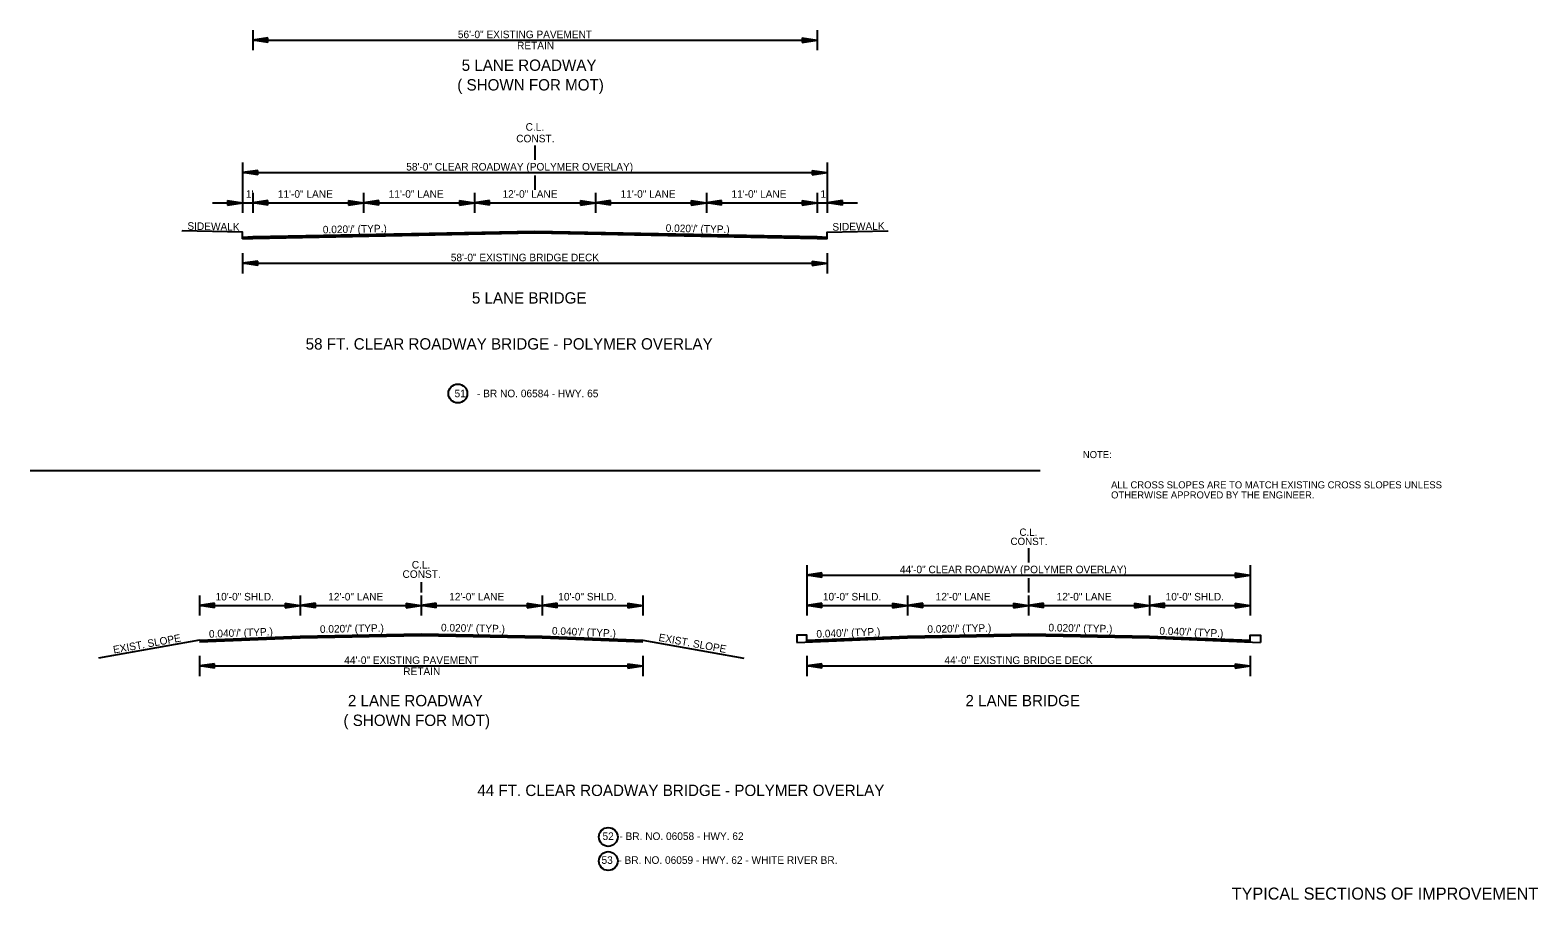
# Model space of a CAD drawing. Extents: x 550980 to 1930787, y -1972975 to 596640.
# Drawn here: x 551050 to 552546, y -1969226 to -1968363 of the extents above; entities that cross this region are included whole.
import ezdxf

# ---------------------------------------------------------------- set-up
doc = ezdxf.new("R2010")
doc.units = 0
for name, color, linetype in [('R_Border', 7, 'Continuous'), ('R_Border Notes', 7, 'Continuous'), ('R_Draft', 7, 'Continuous')]:
    doc.layers.add(name, color=color, linetype=linetype)

# ---------------------------------------------------------------- blocks, each defined once
blk = doc.blocks.new('ARROW')
at = {"layer": 'R_Draft'}
for p, q in [((-2, 0.3), (0, 0)), ((-2, 0.3), (-2, -0.3)), ((-2, 0.25), (-0.334, 0)), ((-2, 0.199), (-0.678, 0)), ((-2, 0.149), (-1.011, 0)), ((-2, 0.097), (-1.35, 0)), ((-2, 0.047), (-1.684, 0)), ((-2, -0.3), (0, 0)), ((-2, -0.098), (-1.35, 0)), ((-2, -0.199), (-0.678, 0)), ((-2, -0.25), (-0.334, 0)), ((-2, -0.149), (-1.011, 0)), ((-2, -0.047), (-1.684, 0))]:
    blk.add_line(p, q, dxfattribs=at)
blk = doc.blocks.new('BPPOLY')
at = {"layer": 'R_Border'}
blk.add_circle((0, 0), 9.34, dxfattribs=at)

msp = doc.modelspace()

# ---------------------------------------------------------------- linework, layer by layer
at = {"layer": 'R_Border'}
for p, q in [((551271.1, -1968362.7), (551271.1, -1968382.7)), ((551831.1, -1968362.7), (551831.1, -1968382.7)), ((551286.1, -1968370.5), (551271.1, -1968372.7)), ((551271.1, -1968372.7), (551831.1, -1968372.7)), ((551286.1, -1968375), (551271.1, -1968372.7)), ((551286.1, -1968370.9), (551273.6, -1968372.7)), ((551286.1, -1968374.6), (551273.6, -1968372.7)), ((551286.1, -1968371.2), (551276.2, -1968372.7)), ((551286.1, -1968374.2), (551276.2, -1968372.7)), ((551286.1, -1968371.6), (551278.7, -1968372.7)), ((551286.1, -1968373.9), (551278.7, -1968372.7)), ((551286.1, -1968372), (551281.2, -1968372.7)), ((551286.1, -1968373.5), (551281.2, -1968372.7)), ((551286.1, -1968372.4), (551283.7, -1968372.7)), ((551286.1, -1968373.1), (551283.7, -1968372.7)), ((551286.1, -1968375), (551286.1, -1968370.5)), ((551816.1, -1968370.5), (551831.1, -1968372.7)), ((551816.1, -1968370.5), (551816.1, -1968375)), ((551816.1, -1968370.9), (551828.6, -1968372.7)), ((551816.1, -1968371.2), (551826, -1968372.7)), ((551816.1, -1968371.6), (551823.5, -1968372.7)), ((551816.1, -1968372), (551821, -1968372.7)), ((551816.1, -1968372.4), (551818.5, -1968372.7)), ((551816.1, -1968375), (551831.1, -1968372.7)), ((551816.1, -1968373.5), (551821, -1968372.7)), ((551816.1, -1968374.2), (551826, -1968372.7)), ((551816.1, -1968374.6), (551828.6, -1968372.7)), ((551816.1, -1968373.9), (551823.5, -1968372.7)), ((551816.1, -1968373.1), (551818.5, -1968372.7)), ((551551.1, -1968477), (551551.1, -1968491.5)), ((551261.1, -1968494), (551261.1, -1968544)), ((551276.1, -1968501.8), (551261.1, -1968504)), ((551261.1, -1968504), (551841.1, -1968504)), ((551276.1, -1968506.3), (551261.1, -1968504)), ((551276.1, -1968502.1), (551263.6, -1968504)), ((551276.1, -1968505.9), (551263.6, -1968504)), ((551276.1, -1968502.5), (551266.2, -1968504)), ((551276.1, -1968505.5), (551266.2, -1968504)), ((551276.1, -1968502.9), (551268.7, -1968504)), ((551276.1, -1968505.1), (551268.7, -1968504)), ((551276.1, -1968503.3), (551271.2, -1968504)), ((551276.1, -1968504.7), (551271.2, -1968504)), ((551276.1, -1968503.7), (551273.7, -1968504)), ((551276.1, -1968504.4), (551273.7, -1968504)), ((551276.1, -1968506.3), (551276.1, -1968501.8)), ((551826.1, -1968501.8), (551841.1, -1968504)), ((551826.1, -1968501.8), (551826.1, -1968506.3)), ((551826.1, -1968502.1), (551838.6, -1968504)), ((551826.1, -1968502.5), (551836, -1968504)), ((551826.1, -1968502.9), (551833.5, -1968504)), ((551826.1, -1968503.3), (551831, -1968504)), ((551826.1, -1968503.7), (551828.5, -1968504)), ((551826.1, -1968506.3), (551841.1, -1968504)), ((551826.1, -1968504.8), (551831, -1968504)), ((551826.1, -1968505.5), (551836, -1968504)), ((551826.1, -1968505.9), (551838.6, -1968504)), ((551826.1, -1968505.1), (551833.5, -1968504)), ((551826.1, -1968504.4), (551828.5, -1968504)), ((551841.1, -1968494), (551841.1, -1968544)), ((551551.1, -1968507), (551551.1, -1968521)), ((551231.1, -1968534), (551871.1, -1968534)), ((551246.1, -1968531.8), (551261.1, -1968534)), ((551246.1, -1968531.8), (551246.1, -1968536.3)), ((551246.1, -1968532.1), (551258.6, -1968534)), ((551246.1, -1968532.5), (551256, -1968534)), ((551246.1, -1968532.9), (551253.5, -1968534)), ((551246.1, -1968533.3), (551251, -1968534)), ((551246.1, -1968533.7), (551248.5, -1968534)), ((551246.1, -1968536.3), (551261.1, -1968534)), ((551246.1, -1968534.8), (551251, -1968534)), ((551246.1, -1968535.5), (551256, -1968534)), ((551246.1, -1968535.9), (551258.6, -1968534)), ((551246.1, -1968535.1), (551253.5, -1968534)), ((551246.1, -1968534.4), (551248.5, -1968534)), ((551271.1, -1968524), (551271.1, -1968544)), ((551286.1, -1968531.8), (551271.1, -1968534)), ((551286.1, -1968536.3), (551271.1, -1968534)), ((551286.1, -1968532.1), (551273.6, -1968534)), ((551286.1, -1968535.9), (551273.6, -1968534)), ((551286.1, -1968532.5), (551276.2, -1968534)), ((551286.1, -1968535.5), (551276.2, -1968534)), ((551286.1, -1968532.9), (551278.7, -1968534)), ((551286.1, -1968535.1), (551278.7, -1968534)), ((551286.1, -1968533.3), (551281.2, -1968534)), ((551286.1, -1968534.7), (551281.2, -1968534)), ((551286.1, -1968533.7), (551283.7, -1968534)), ((551286.1, -1968534.4), (551283.7, -1968534)), ((551286.1, -1968536.3), (551286.1, -1968531.8)), ((551366.1, -1968531.8), (551381.1, -1968534)), ((551366.1, -1968531.8), (551366.1, -1968536.3)), ((551366.1, -1968532.1), (551378.6, -1968534)), ((551366.1, -1968532.5), (551376, -1968534)), ((551366.1, -1968532.9), (551373.5, -1968534)), ((551366.1, -1968533.3), (551371, -1968534)), ((551366.1, -1968533.7), (551368.5, -1968534)), ((551366.1, -1968536.3), (551381.1, -1968534)), ((551366.1, -1968534.8), (551371, -1968534)), ((551366.1, -1968535.5), (551376, -1968534)), ((551366.1, -1968535.9), (551378.6, -1968534)), ((551366.1, -1968535.1), (551373.5, -1968534)), ((551366.1, -1968534.4), (551368.5, -1968534)), ((551381.1, -1968524), (551381.1, -1968544)), ((551396.1, -1968531.8), (551381.1, -1968534)), ((551396.1, -1968536.3), (551381.1, -1968534)), ((551396.1, -1968532.1), (551383.6, -1968534)), ((551396.1, -1968535.9), (551383.6, -1968534)), ((551396.1, -1968532.5), (551386.2, -1968534)), ((551396.1, -1968535.5), (551386.2, -1968534)), ((551396.1, -1968532.9), (551388.7, -1968534)), ((551396.1, -1968535.1), (551388.7, -1968534)), ((551396.1, -1968533.3), (551391.2, -1968534)), ((551396.1, -1968534.7), (551391.2, -1968534)), ((551396.1, -1968533.7), (551393.7, -1968534)), ((551396.1, -1968534.4), (551393.7, -1968534)), ((551396.1, -1968536.3), (551396.1, -1968531.8)), ((551476.1, -1968531.8), (551491.1, -1968534)), ((551476.1, -1968531.8), (551476.1, -1968536.3)), ((551476.1, -1968532.1), (551488.6, -1968534)), ((551476.1, -1968532.5), (551486, -1968534)), ((551476.1, -1968532.9), (551483.5, -1968534)), ((551476.1, -1968533.3), (551481, -1968534)), ((551476.1, -1968533.7), (551478.5, -1968534)), ((551476.1, -1968536.3), (551491.1, -1968534)), ((551476.1, -1968534.8), (551481, -1968534)), ((551476.1, -1968535.5), (551486, -1968534)), ((551476.1, -1968535.9), (551488.6, -1968534)), ((551476.1, -1968535.1), (551483.5, -1968534)), ((551476.1, -1968534.4), (551478.5, -1968534)), ((551491.1, -1968524), (551491.1, -1968544)), ((551506.1, -1968531.8), (551491.1, -1968534)), ((551506.1, -1968536.3), (551491.1, -1968534)), ((551506.1, -1968532.1), (551493.6, -1968534)), ((551506.1, -1968535.9), (551493.6, -1968534)), ((551506.1, -1968532.5), (551496.2, -1968534)), ((551506.1, -1968535.5), (551496.2, -1968534)), ((551506.1, -1968532.9), (551498.7, -1968534)), ((551506.1, -1968535.1), (551498.7, -1968534)), ((551506.1, -1968533.3), (551501.2, -1968534)), ((551506.1, -1968534.7), (551501.2, -1968534)), ((551506.1, -1968533.7), (551503.7, -1968534)), ((551506.1, -1968534.4), (551503.7, -1968534)), ((551506.1, -1968536.3), (551506.1, -1968531.8)), ((551596.1, -1968531.8), (551611.1, -1968534)), ((551596.1, -1968531.8), (551596.1, -1968536.3)), ((551596.1, -1968532.1), (551608.6, -1968534)), ((551596.1, -1968532.5), (551606, -1968534)), ((551596.1, -1968532.9), (551603.5, -1968534)), ((551596.1, -1968533.3), (551601, -1968534)), ((551596.1, -1968533.7), (551598.5, -1968534)), ((551596.1, -1968536.3), (551611.1, -1968534)), ((551596.1, -1968534.8), (551601, -1968534)), ((551596.1, -1968535.5), (551606, -1968534)), ((551596.1, -1968535.9), (551608.6, -1968534)), ((551596.1, -1968535.1), (551603.5, -1968534)), ((551596.1, -1968534.4), (551598.5, -1968534)), ((551611.1, -1968524), (551611.1, -1968544)), ((551626.1, -1968531.8), (551611.1, -1968534)), ((551626.1, -1968536.3), (551611.1, -1968534)), ((551626.1, -1968532.1), (551613.6, -1968534)), ((551626.1, -1968535.9), (551613.6, -1968534)), ((551626.1, -1968532.5), (551616.2, -1968534)), ((551626.1, -1968535.5), (551616.2, -1968534)), ((551626.1, -1968532.9), (551618.7, -1968534)), ((551626.1, -1968535.1), (551618.7, -1968534)), ((551626.1, -1968533.3), (551621.2, -1968534)), ((551626.1, -1968534.7), (551621.2, -1968534)), ((551626.1, -1968533.7), (551623.7, -1968534)), ((551626.1, -1968534.4), (551623.7, -1968534)), ((551626.1, -1968536.3), (551626.1, -1968531.8)), ((551706.1, -1968531.8), (551721.1, -1968534)), ((551706.1, -1968531.8), (551706.1, -1968536.3)), ((551706.1, -1968532.1), (551718.6, -1968534)), ((551706.1, -1968532.5), (551716, -1968534)), ((551706.1, -1968532.9), (551713.5, -1968534)), ((551706.1, -1968533.3), (551711, -1968534)), ((551706.1, -1968533.7), (551708.5, -1968534)), ((551706.1, -1968536.3), (551721.1, -1968534)), ((551706.1, -1968534.8), (551711, -1968534)), ((551706.1, -1968535.5), (551716, -1968534)), ((551706.1, -1968535.9), (551718.6, -1968534)), ((551706.1, -1968535.1), (551713.5, -1968534)), ((551706.1, -1968534.4), (551708.5, -1968534)), ((551721.1, -1968524), (551721.1, -1968544)), ((551736.1, -1968531.8), (551721.1, -1968534)), ((551736.1, -1968536.3), (551721.1, -1968534)), ((551736.1, -1968532.1), (551723.6, -1968534)), ((551736.1, -1968535.9), (551723.6, -1968534)), ((551736.1, -1968532.5), (551726.2, -1968534)), ((551736.1, -1968535.5), (551726.2, -1968534)), ((551736.1, -1968532.9), (551728.7, -1968534)), ((551736.1, -1968535.1), (551728.7, -1968534)), ((551736.1, -1968533.3), (551731.2, -1968534)), ((551736.1, -1968534.7), (551731.2, -1968534)), ((551736.1, -1968533.7), (551733.7, -1968534)), ((551736.1, -1968534.4), (551733.7, -1968534)), ((551736.1, -1968536.3), (551736.1, -1968531.8)), ((551816.1, -1968531.8), (551831.1, -1968534)), ((551816.1, -1968531.8), (551816.1, -1968536.3)), ((551816.1, -1968532.1), (551828.6, -1968534)), ((551816.1, -1968532.5), (551826, -1968534)), ((551816.1, -1968532.9), (551823.5, -1968534)), ((551816.1, -1968533.3), (551821, -1968534)), ((551816.1, -1968533.7), (551818.5, -1968534)), ((551816.1, -1968536.3), (551831.1, -1968534)), ((551816.1, -1968534.8), (551821, -1968534)), ((551816.1, -1968535.5), (551826, -1968534)), ((551816.1, -1968535.9), (551828.6, -1968534)), ((551816.1, -1968535.1), (551823.5, -1968534)), ((551816.1, -1968534.4), (551818.5, -1968534)), ((551831.1, -1968524), (551831.1, -1968544)), ((551856.1, -1968531.8), (551841.1, -1968534)), ((551856.1, -1968536.3), (551841.1, -1968534)), ((551856.1, -1968532.1), (551843.6, -1968534)), ((551856.1, -1968535.9), (551843.6, -1968534)), ((551856.1, -1968532.5), (551846.2, -1968534)), ((551856.1, -1968535.5), (551846.2, -1968534)), ((551856.1, -1968532.9), (551848.7, -1968534)), ((551856.1, -1968535.1), (551848.7, -1968534)), ((551856.1, -1968533.3), (551851.2, -1968534)), ((551856.1, -1968534.7), (551851.2, -1968534)), ((551856.1, -1968533.7), (551853.7, -1968534)), ((551856.1, -1968534.4), (551853.7, -1968534)), ((551856.1, -1968536.3), (551856.1, -1968531.8)), ((551261.1, -1968584), (551261.1, -1968604)), ((551276.1, -1968591.8), (551261.1, -1968594)), ((551276.1, -1968592.1), (551263.6, -1968594)), ((551276.1, -1968592.5), (551266.2, -1968594)), ((551276.1, -1968592.9), (551268.7, -1968594)), ((551276.1, -1968593.3), (551271.2, -1968594)), ((551276.1, -1968593.7), (551273.7, -1968594)), ((551276.1, -1968596.3), (551276.1, -1968591.8)), ((551826.1, -1968591.8), (551841.1, -1968594)), ((551826.1, -1968591.8), (551826.1, -1968596.3)), ((551826.1, -1968592.1), (551838.6, -1968594)), ((551826.1, -1968592.5), (551836, -1968594)), ((551826.1, -1968592.9), (551833.5, -1968594)), ((551826.1, -1968593.3), (551831, -1968594)), ((551826.1, -1968593.7), (551828.5, -1968594)), ((551841.1, -1968584), (551841.1, -1968604)), ((551261.1, -1968594), (551841.1, -1968594)), ((551276.1, -1968596.3), (551261.1, -1968594)), ((551276.1, -1968595.9), (551263.6, -1968594)), ((551276.1, -1968595.5), (551266.2, -1968594)), ((551276.1, -1968595.1), (551268.7, -1968594)), ((551276.1, -1968594.7), (551271.2, -1968594)), ((551276.1, -1968594.4), (551273.7, -1968594)), ((551826.1, -1968596.3), (551841.1, -1968594)), ((551826.1, -1968594.8), (551831, -1968594)), ((551826.1, -1968595.5), (551836, -1968594)), ((551826.1, -1968595.9), (551838.6, -1968594)), ((551826.1, -1968595.1), (551833.5, -1968594)), ((551826.1, -1968594.4), (551828.5, -1968594)), ((551050.3, -1968799.7), (552052.2, -1968799.7)), ((552040.7, -1968876.5), (552040.7, -1968891)), ((551820.7, -1968893.5), (551820.7, -1968943.5)), ((551820.7, -1968903.5), (552260.7, -1968903.5)), ((552040.7, -1968906.5), (552040.7, -1968920.5)), ((552260.7, -1968893.5), (552260.7, -1968943.5)), ((551438.2, -1968910.5), (551438.2, -1968920.5)), ((551218.2, -1968923.5), (551218.2, -1968943.5)), ((551218.2, -1968933.5), (551658.2, -1968933.5)), ((551318.2, -1968923.5), (551318.2, -1968943.5)), ((551438.2, -1968923.5), (551438.2, -1968943.5)), ((551558.2, -1968923.5), (551558.2, -1968943.5)), ((551658.2, -1968923.5), (551658.2, -1968943.5)), ((551820.7, -1968933.5), (552260.7, -1968933.5)), ((551920.7, -1968923.5), (551920.7, -1968943.5)), ((552040.7, -1968923.5), (552040.7, -1968943.5)), ((552160.7, -1968923.5), (552160.7, -1968943.5)), ((551218.2, -1968967.9), (551118.2, -1968985.9)), ((551658.2, -1968967.9), (551758.2, -1968985.9)), ((551218.2, -1968983.5), (551218.2, -1969003.5)), ((551218.2, -1968993.5), (551658.2, -1968993.5)), ((551658.2, -1968983.5), (551658.2, -1969003.5)), ((551820.7, -1968983.5), (551820.7, -1969003.5)), ((551820.7, -1968993.5), (552260.7, -1968993.5)), ((552260.7, -1968983.5), (552260.7, -1969003.5))]:
    msp.add_line(p, q, dxfattribs=at)
for points in [[(551261.1, -1968569.8), (551261.1, -1968563), (551201.1, -1968561.8), (551201.1, -1968561.8)], [(551261.1, -1968568), (551271.1, -1968567.6), (551551.1, -1968562), (551831.1, -1968567.6), (551841.1, -1968568)], [(551261.1, -1968568.3), (551271.1, -1968567.9), (551551.1, -1968562.3), (551831.1, -1968567.9), (551841.1, -1968568.3)], [(551261.1, -1968568.6), (551271.1, -1968568.2), (551551.1, -1968562.6), (551831.1, -1968568.2), (551841.1, -1968568.6)], [(551261.1, -1968568.9), (551271.1, -1968568.5), (551551.1, -1968562.9), (551831.1, -1968568.5), (551841.1, -1968568.9)], [(551261.1, -1968569.2), (551271.1, -1968568.8), (551551.1, -1968563.2), (551831.1, -1968568.8), (551841.1, -1968569.2)], [(551261.1, -1968569.5), (551271.1, -1968569.1), (551551.1, -1968563.5), (551831.1, -1968569.1), (551841.1, -1968569.5)], [(551261.1, -1968569.8), (551271.1, -1968569.4), (551551.1, -1968563.8), (551831.1, -1968569.4), (551841.1, -1968569.8)], [(551841.1, -1968569.8), (551841.1, -1968563), (551901.1, -1968561.8), (551901.1, -1968561.8)], [(551218.2, -1968967.9), (551318.2, -1968963.9), (551438.2, -1968961.5), (551558.2, -1968963.9), (551658.2, -1968967.9)], [(551218.2, -1968968.2), (551318.2, -1968964.2), (551438.2, -1968961.8), (551558.2, -1968964.2), (551658.2, -1968968.2)], [(551218.2, -1968968.5), (551318.2, -1968964.5), (551438.2, -1968962.1), (551558.2, -1968964.5), (551658.2, -1968968.5)], [(551218.2, -1968968.8), (551318.2, -1968964.8), (551438.2, -1968962.4), (551558.2, -1968964.8), (551658.2, -1968968.8)], [(551218.2, -1968969.1), (551318.2, -1968965.1), (551438.2, -1968962.7), (551558.2, -1968965.1), (551658.2, -1968969.1)], [(551218.2, -1968969.4), (551318.2, -1968965.4), (551438.2, -1968963), (551558.2, -1968965.4), (551658.2, -1968969.4)], [(551218.2, -1968969.7), (551318.2, -1968965.7), (551438.2, -1968963.3), (551558.2, -1968965.7), (551658.2, -1968969.7)], [(551820.7, -1968969.4), (551820.7, -1968962.9), (551810.7, -1968962.9), (551810.7, -1968970.1)], [(551810.7, -1968970.1), (551920.7, -1968965.7), (552040.7, -1968963.3), (552160.7, -1968965.7), (552270.7, -1968970.1)], [(551820.7, -1968967.9), (551920.7, -1968963.9), (552040.7, -1968961.5), (552160.7, -1968963.9), (552260.7, -1968967.9)], [(551820.7, -1968968.2), (551920.7, -1968964.2), (552040.7, -1968961.8), (552160.7, -1968964.2), (552260.7, -1968968.2)], [(551820.7, -1968968.5), (551920.7, -1968964.5), (552040.7, -1968962.1), (552160.7, -1968964.5), (552260.7, -1968968.5)], [(551820.7, -1968968.8), (551920.7, -1968964.8), (552040.7, -1968962.4), (552160.7, -1968964.8), (552260.7, -1968968.8)], [(551820.7, -1968969.1), (551920.7, -1968965.1), (552040.7, -1968962.7), (552160.7, -1968965.1), (552260.7, -1968969.1)], [(551820.7, -1968969.4), (551920.7, -1968965.4), (552040.7, -1968963), (552160.7, -1968965.4), (552260.7, -1968969.4)], [(552260.7, -1968970.1), (552260.7, -1968962.9), (552270.7, -1968962.9), (552270.7, -1968970.1)]]:
    msp.add_lwpolyline(points, dxfattribs=at)
for centre in [(551623.8, -1969163.1), (551623.8, -1969187)]:
    msp.add_circle(centre, 9.34, dxfattribs=at)

# ---------------------------------------------------------------- block references
msp.add_blockref('BPPOLY', (551474.6, -1968723.2), dxfattribs=at)
at = {"layer": 'R_Border', "xscale": 7.5, "yscale": 7.5, "rotation": 180}
for p in [(551820.7, -1968903.5), (551218.2, -1968933.5), (551318.2, -1968933.5), (551438.2, -1968933.5), (551558.2, -1968933.5), (551820.7, -1968933.5), (551920.7, -1968933.5), (552040.7, -1968933.5), (552160.7, -1968933.5), (551218.2, -1968993.5), (551820.7, -1968993.5)]:
    msp.add_blockref('ARROW', p, dxfattribs=at)
at = {"layer": 'R_Border', "xscale": 7.5, "yscale": 7.5}
for p in [(552260.7, -1968903.5), (551318.2, -1968933.5), (551438.2, -1968933.5), (551558.2, -1968933.5), (551658.2, -1968933.5), (551920.7, -1968933.5), (552040.7, -1968933.5), (552160.7, -1968933.5), (552260.7, -1968933.5), (551658.2, -1968993.5), (552260.7, -1968993.5)]:
    msp.add_blockref('ARROW', p, dxfattribs=at)

# ---------------------------------------------------------------- texts
at = {"layer": 'R_Border'}
for s, height, p in [('56\'-0" EXISTING PAVEMENT', 7.5, (551474.6, -1968370.7)), ('RETAIN', 7.5, (551533.3, -1968381.7)), ('5 LANE ROADWAY', 11.25, (551478.4, -1968403.1)), ('( SHOWN FOR MOT)', 11.25, (551474, -1968422.6)), ('C.L.', 7.5, (551541.8, -1968462.5)), ('CONST.', 7.5, (551532.5, -1968474)), ('58\'-0" CLEAR ROADWAY (POLYMER OVERLAY)', 7.5, (551423.4, -1968502)), ("1'", 7.5, (551264.3, -1968529)), ('11\'-0" LANE', 7.5, (551296, -1968529)), ('11\'-0" LANE', 7.5, (551406, -1968529)), ('12\'-0" LANE', 7.5, (551518.9, -1968529)), ('11\'-0" LANE', 7.5, (551636, -1968529)), ('11\'-0" LANE', 7.5, (551746, -1968529)), ("1'", 7.5, (551834.3, -1968529)), ('58\'-0" EXISTING BRIDGE DECK', 7.5, (551467.6, -1968592)), ('5 LANE BRIDGE', 11.25, (551488.5, -1968634)), ('58 FT. CLEAR ROADWAY BRIDGE - POLYMER OVERLAY', 11.25, (551323.6, -1968679.6)), ('51', 7.5, (551471.3, -1968726.9)), ('- BR NO. 06584 - HWY. 65', 7.5, (551493.6, -1968726.9)), ('C.L.', 7.25, (552031.7, -1968864.4)), ('CONST.', 7.25, (552022.8, -1968873.5)), ('C.L.', 7.5, (551428.9, -1968896.8)), ('CONST.', 7.5, (551419.7, -1968906.1)), ('44\'-0" CLEAR ROADWAY (POLYMER OVERLAY)', 7.5, (551913.1, -1968901.5)), ('10\'-0" SHLD.', 7.5, (551234.2, -1968928.5)), ('12\'-0" LANE', 7.5, (551346, -1968928.5)), ('12\'-0" LANE', 7.5, (551466, -1968928.5)), ('10\'-0" SHLD.', 7.5, (551574.2, -1968928.5)), ('10\'-0" SHLD.', 7.5, (551836.7, -1968928.5)), ('12\'-0" LANE', 7.5, (551948.6, -1968928.5)), ('12\'-0" LANE', 7.5, (552068.6, -1968928.5)), ('10\'-0" SHLD.', 7.5, (552176.7, -1968928.5)), ('44\'-0" EXISTING PAVEMENT', 7.5, (551361.9, -1968991.5)), ('RETAIN', 7.5, (551420.4, -1969002.5)), ('44\'-0" EXISTING BRIDGE DECK', 7.5, (551957.3, -1968991.5)), ('2 LANE ROADWAY', 11.25, (551365.5, -1969033.5)), ('2 LANE BRIDGE', 11.25, (551978.1, -1969033.5)), ('( SHOWN FOR MOT)', 11.25, (551361.1, -1969053)), ('44 FT. CLEAR ROADWAY BRIDGE - POLYMER OVERLAY', 11.25, (551493.9, -1969122.5))]:
    msp.add_text(s, height=height, dxfattribs=at).set_placement(p)
for s, height, rotation, p in [('SIDEWALK', 7.5, 358.8542, (551206.2, -1968560.7)), ("0.020'/' (TYP.)", 7.5, 1.1458, (551340.7, -1968564.4)), ("0.020'/' (TYP.)", 7.5, 358.8542, (551680.7, -1968562.8)), ('SIDEWALK', 7.5, 1.1458, (551846.2, -1968561.7)), ("0.020'/' (TYP.)", 7.5, 1.1458, (551337.8, -1968960.7)), ("0.020'/' (TYP.)", 7.5, 358.8542, (551457.8, -1968959.1)), ("0.020'/' (TYP.)", 7.5, 1.1458, (551940.4, -1968960.7)), ("0.020'/' (TYP.)", 7.5, 358.8542, (552060.4, -1968959.1)), ('EXIST. SLOPE', 7.5, 10.204, (551133.3, -1968981.2)), ("0.040'/' (TYP.)", 7.5, 2.2916, (551227.8, -1968965.5)), ("0.040'/' (TYP.)", 7.5, 357.7084, (551567.8, -1968962.3)), ('EXIST. SLOPE', 7.5, 349.796, (551673.3, -1968968.6)), ("0.040'/' (TYP.)", 7.5, 2.2916, (551830.4, -1968965.5)), ("0.040'/' (TYP.)", 7.5, 357.7084, (552170.4, -1968962.3)), ('TYPICAL SECTIONS OF IMPROVEMENT', 12, 360, (552242.3, -1969225.3))]:
    msp.add_text(s, height=height, rotation=rotation, dxfattribs=at).set_placement(p)
at = {"layer": 'R_Border Notes'}
for s, p in [('NOTE: ', (552094.6, -1968787.3)), ('ALL CROSS SLOPES ARE TO MATCH EXISTING CROSS SLOPES UNLESS ', (552122.6, -1968817.3)), ('OTHERWISE APPROVED BY THE ENGINEER.', (552122.6, -1968827.3))]:
    msp.add_text(s, height=7, dxfattribs=at).set_placement(p)
at = {"layer": 'R_Draft'}
for s, p in [('52  - BR. NO. 06058 - HWY. 62', (551618.1, -1969166.1)), ('53  - BR. NO. 06059 - HWY. 62 - WHITE RIVER BR.', (551617.1, -1969189.8))]:
    msp.add_text(s, height=7.5, dxfattribs=at).set_placement(p)

doc.saveas('drawing.dxf')
